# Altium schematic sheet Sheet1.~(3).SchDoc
size A4; SheetNumber: 1; SheetTotal: 1
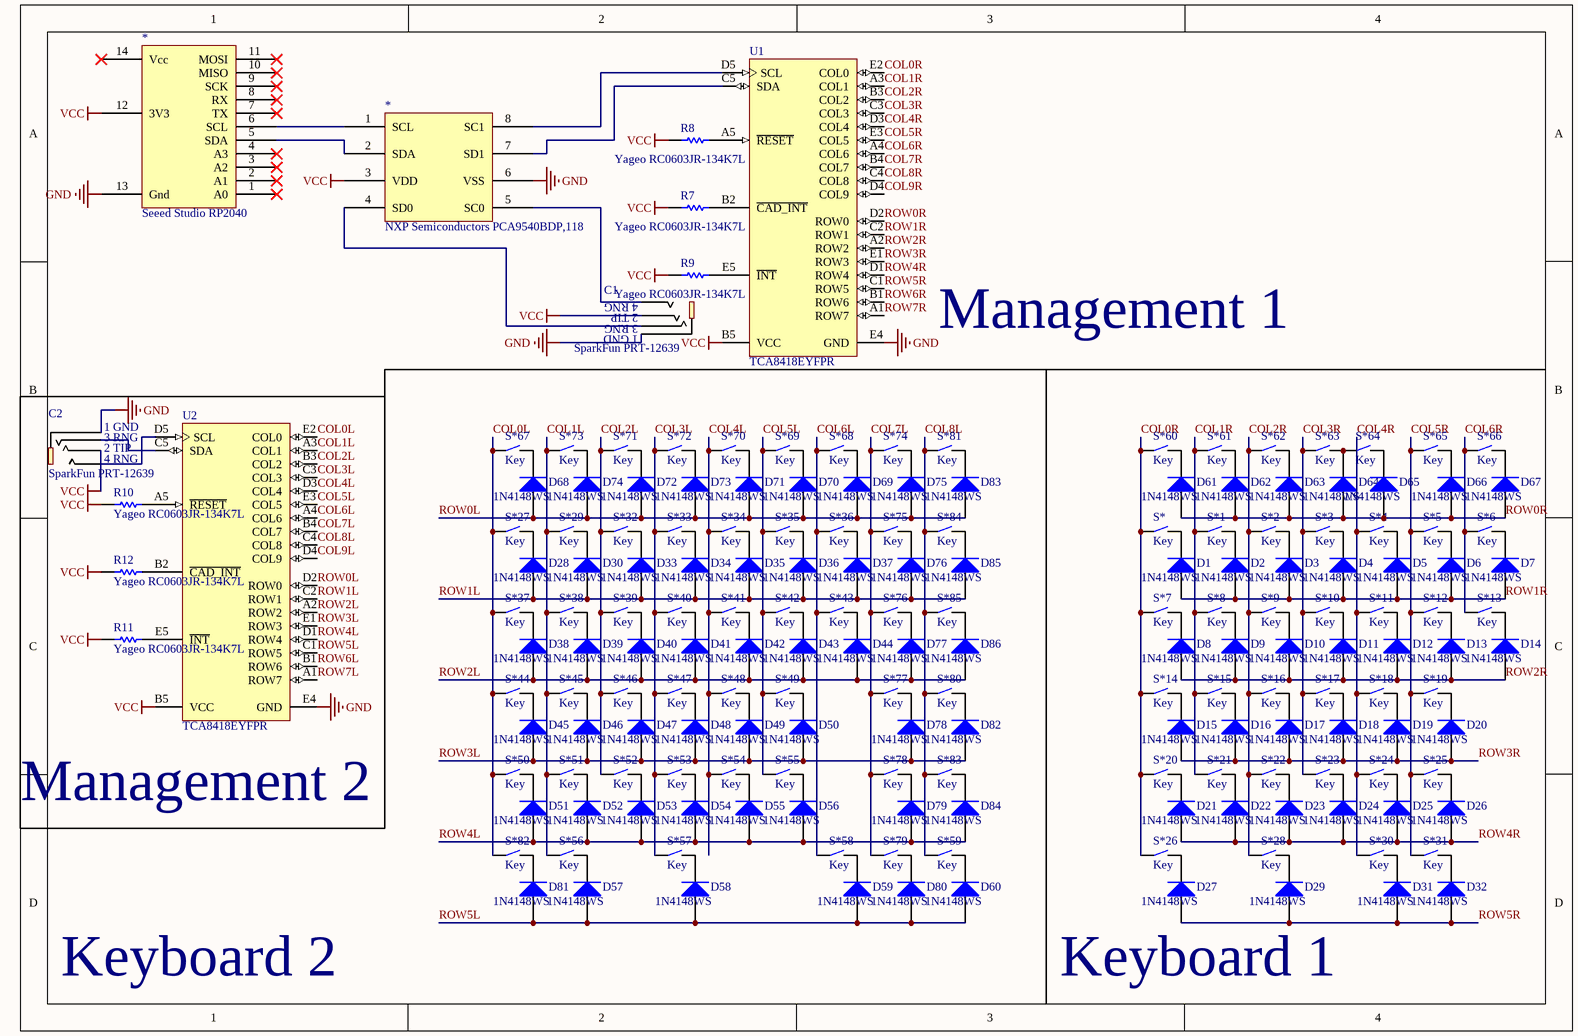
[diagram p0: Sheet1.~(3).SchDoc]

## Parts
(Parts that share a designator on the sheet are numbered #1, #2 ... from top to bottom, then left to right.)
*#1  Seeed Studio RP2040  [Seeed Studio 102010328-Footprint-2]
*#2  NXP Semiconductors PCA9540BDP,118  [TSSOP-ST8_M]
C1  SparkFun PRT-12639  [PCB-gnlnaqw4so214acln296-1]
C2  SparkFun PRT-12639  [PCB-gnlnaqw4so214acln296-1]
D1  1N4148WS  [SODFL250X100-2N]
D2  1N4148WS  [SODFL250X100-2N]
D3  1N4148WS  [SODFL250X100-2N]
D4  1N4148WS  [SODFL250X100-2N]
D5  1N4148WS  [SODFL250X100-2N]
D6  1N4148WS  [SODFL250X100-2N]
D7  1N4148WS  [SODFL250X100-2N]
D8  1N4148WS  [SODFL250X100-2N]
D9  1N4148WS  [SODFL250X100-2N]
D10  1N4148WS  [SODFL250X100-2N]
D11  1N4148WS  [SODFL250X100-2N]
D12  1N4148WS  [SODFL250X100-2N]
D13  1N4148WS  [SODFL250X100-2N]
D14  1N4148WS  [SODFL250X100-2N]
D15  1N4148WS  [SODFL250X100-2N]
D16  1N4148WS  [SODFL250X100-2N]
D17  1N4148WS  [SODFL250X100-2N]
D18  1N4148WS  [SODFL250X100-2N]
D19  1N4148WS  [SODFL250X100-2N]
D20  1N4148WS  [SODFL250X100-2N]
D21  1N4148WS  [SODFL250X100-2N]
D22  1N4148WS  [SODFL250X100-2N]
D23  1N4148WS  [SODFL250X100-2N]
D24  1N4148WS  [SODFL250X100-2N]
D25  1N4148WS  [SODFL250X100-2N]
D26  1N4148WS  [SODFL250X100-2N]
D27  1N4148WS  [SODFL250X100-2N]
D28  1N4148WS  [SODFL250X100-2N]
D29  1N4148WS  [SODFL250X100-2N]
D30  1N4148WS  [SODFL250X100-2N]
D31  1N4148WS  [SODFL250X100-2N]
D32  1N4148WS  [SODFL250X100-2N]
D33  1N4148WS  [SODFL250X100-2N]
D34  1N4148WS  [SODFL250X100-2N]
D35  1N4148WS  [SODFL250X100-2N]
D36  1N4148WS  [SODFL250X100-2N]
D37  1N4148WS  [SODFL250X100-2N]
D38  1N4148WS  [SODFL250X100-2N]
D39  1N4148WS  [SODFL250X100-2N]
D40  1N4148WS  [SODFL250X100-2N]
D41  1N4148WS  [SODFL250X100-2N]
D42  1N4148WS  [SODFL250X100-2N]
D43  1N4148WS  [SODFL250X100-2N]
D44  1N4148WS  [SODFL250X100-2N]
D45  1N4148WS  [SODFL250X100-2N]
D46  1N4148WS  [SODFL250X100-2N]
D47  1N4148WS  [SODFL250X100-2N]
D48  1N4148WS  [SODFL250X100-2N]
D49  1N4148WS  [SODFL250X100-2N]
D50  1N4148WS  [SODFL250X100-2N]
D51  1N4148WS  [SODFL250X100-2N]
D52  1N4148WS  [SODFL250X100-2N]
D53  1N4148WS  [SODFL250X100-2N]
D54  1N4148WS  [SODFL250X100-2N]
D55  1N4148WS  [SODFL250X100-2N]
D56  1N4148WS  [SODFL250X100-2N]
D57  1N4148WS  [SODFL250X100-2N]
D58  1N4148WS  [SODFL250X100-2N]
D59  1N4148WS  [SODFL250X100-2N]
D60  1N4148WS  [SODFL250X100-2N]
D61  1N4148WS  [SODFL250X100-2N]
D62  1N4148WS  [SODFL250X100-2N]
D63  1N4148WS  [SODFL250X100-2N]
D64  1N4148WS  [SODFL250X100-2N]
D65  1N4148WS  [SODFL250X100-2N]
D66  1N4148WS  [SODFL250X100-2N]
D67  1N4148WS  [SODFL250X100-2N]
D68  1N4148WS  [SODFL250X100-2N]
D69  1N4148WS  [SODFL250X100-2N]
D70  1N4148WS  [SODFL250X100-2N]
D71  1N4148WS  [SODFL250X100-2N]
D72  1N4148WS  [SODFL250X100-2N]
D73  1N4148WS  [SODFL250X100-2N]
D74  1N4148WS  [SODFL250X100-2N]
D75  1N4148WS  [SODFL250X100-2N]
D76  1N4148WS  [SODFL250X100-2N]
D77  1N4148WS  [SODFL250X100-2N]
D78  1N4148WS  [SODFL250X100-2N]
D79  1N4148WS  [SODFL250X100-2N]
D80  1N4148WS  [SODFL250X100-2N]
D81  1N4148WS  [SODFL250X100-2N]
D82  1N4148WS  [SODFL250X100-2N]
D83  1N4148WS  [SODFL250X100-2N]
D84  1N4148WS  [SODFL250X100-2N]
D85  1N4148WS  [SODFL250X100-2N]
D86  1N4148WS  [SODFL250X100-2N]
R7  Yageo RC0603JR-134K7L  [RESC1608X55X25LL10T15]
R8  Yageo RC0603JR-134K7L  [RESC1608X55X25LL10T15]
R9  Yageo RC0603JR-134K7L  [RESC1608X55X25LL10T15]
R10  Yageo RC0603JR-134K7L  [RESC1608X55X25LL10T15]
R11  Yageo RC0603JR-134K7L  [RESC1608X55X25LL10T15]
R12  Yageo RC0603JR-134K7L  [RESC1608X55X25LL10T15]
S*  Key  [Adafruit Industries 4958-Footprint-1]
S*1  Key  [Adafruit Industries 4958-Footprint-1]
S*2  Key  [Adafruit Industries 4958-Footprint-1]
S*3  Key  [Adafruit Industries 4958-Footprint-1]
S*4  Key  [Adafruit Industries 4958-Footprint-1]
S*5  Key  [Adafruit Industries 4958-Footprint-1]
S*6  Key  [Adafruit Industries 4958-Footprint-1]
S*7  Key  [Adafruit Industries 4958-Footprint-1]
S*8  Key  [Adafruit Industries 4958-Footprint-1]
S*9  Key  [Adafruit Industries 4958-Footprint-1]
S*10  Key  [Adafruit Industries 4958-Footprint-1]
S*11  Key  [Adafruit Industries 4958-Footprint-1]
S*12  Key  [Adafruit Industries 4958-Footprint-1]
S*13  Key  [Adafruit Industries 4958-Footprint-1]
S*14  Key  [Adafruit Industries 4958-Footprint-1]
S*15  Key  [Adafruit Industries 4958-Footprint-1]
S*16  Key  [Adafruit Industries 4958-Footprint-1]
S*17  Key  [Adafruit Industries 4958-Footprint-1]
S*18  Key  [Adafruit Industries 4958-Footprint-1]
S*19  Key  [Adafruit Industries 4958-Footprint-1]
S*20  Key  [Adafruit Industries 4958-Footprint-1]
S*21  Key  [Adafruit Industries 4958-Footprint-1]
S*22  Key  [Adafruit Industries 4958-Footprint-1]
S*23  Key  [Adafruit Industries 4958-Footprint-1]
S*24  Key  [Adafruit Industries 4958-Footprint-1]
S*25  Key  [Adafruit Industries 4958-Footprint-1]
S*26  Key  [Adafruit Industries 4958-Footprint-1]
S*27  Key  [Adafruit Industries 4958-Footprint-1]
S*28  Key  [Adafruit Industries 4958-Footprint-1]
S*29  Key  [Adafruit Industries 4958-Footprint-1]
S*30  Key  [Adafruit Industries 4958-Footprint-1]
S*31  Key  [Adafruit Industries 4958-Footprint-1]
S*32  Key  [Adafruit Industries 4958-Footprint-1]
S*33  Key  [Adafruit Industries 4958-Footprint-1]
S*34  Key  [Adafruit Industries 4958-Footprint-1]
S*35  Key  [Adafruit Industries 4958-Footprint-1]
S*36  Key  [Adafruit Industries 4958-Footprint-1]
S*37  Key  [Adafruit Industries 4958-Footprint-1]
S*38  Key  [Adafruit Industries 4958-Footprint-1]
S*39  Key  [Adafruit Industries 4958-Footprint-1]
S*40  Key  [Adafruit Industries 4958-Footprint-1]
S*41  Key  [Adafruit Industries 4958-Footprint-1]
S*42  Key  [Adafruit Industries 4958-Footprint-1]
S*43  Key  [Adafruit Industries 4958-Footprint-1]
S*44  Key  [Adafruit Industries 4958-Footprint-1]
S*45  Key  [Adafruit Industries 4958-Footprint-1]
S*46  Key  [Adafruit Industries 4958-Footprint-1]
S*47  Key  [Adafruit Industries 4958-Footprint-1]
S*48  Key  [Adafruit Industries 4958-Footprint-1]
S*49  Key  [Adafruit Industries 4958-Footprint-1]
S*50  Key  [Adafruit Industries 4958-Footprint-1]
S*51  Key  [Adafruit Industries 4958-Footprint-1]
S*52  Key  [Adafruit Industries 4958-Footprint-1]
S*53  Key  [Adafruit Industries 4958-Footprint-1]
S*54  Key  [Adafruit Industries 4958-Footprint-1]
S*55  Key  [Adafruit Industries 4958-Footprint-1]
S*56  Key  [Adafruit Industries 4958-Footprint-1]
S*57  Key  [Adafruit Industries 4958-Footprint-1]
S*58  Key  [Adafruit Industries 4958-Footprint-1]
S*59  Key  [Adafruit Industries 4958-Footprint-1]
S*60  Key  [Adafruit Industries 4958-Footprint-1]
S*61  Key  [Adafruit Industries 4958-Footprint-1]
S*62  Key  [Adafruit Industries 4958-Footprint-1]
S*63  Key  [Adafruit Industries 4958-Footprint-1]
S*64  Key  [Adafruit Industries 4958-Footprint-1]
S*65  Key  [Adafruit Industries 4958-Footprint-1]
S*66  Key  [Adafruit Industries 4958-Footprint-1]
S*67  Key  [Adafruit Industries 4958-Footprint-1]
S*68  Key  [Adafruit Industries 4958-Footprint-1]
S*69  Key  [Adafruit Industries 4958-Footprint-1]
S*70  Key  [Adafruit Industries 4958-Footprint-1]
S*71  Key  [Adafruit Industries 4958-Footprint-1]
S*72  Key  [Adafruit Industries 4958-Footprint-1]
S*73  Key  [Adafruit Industries 4958-Footprint-1]
S*74  Key  [Adafruit Industries 4958-Footprint-1]
S*75  Key  [Adafruit Industries 4958-Footprint-1]
S*76  Key  [Adafruit Industries 4958-Footprint-1]
S*77  Key  [Adafruit Industries 4958-Footprint-1]
S*78  Key  [Adafruit Industries 4958-Footprint-1]
S*79  Key  [Adafruit Industries 4958-Footprint-1]
S*80  Key  [Adafruit Industries 4958-Footprint-1]
S*81  Key  [Adafruit Industries 4958-Footprint-1]
S*82  Key  [Adafruit Industries 4958-Footprint-1]
S*83  Key  [Adafruit Industries 4958-Footprint-1]
S*84  Key  [Adafruit Industries 4958-Footprint-1]
S*85  Key  [Adafruit Industries 4958-Footprint-1]
U1  TCA8418EYFPR  [YFP25]
U2  TCA8418EYFPR  [YFP25]

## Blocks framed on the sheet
Management 2: C2 R10-R12 U2

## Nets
GND: *#1.13(Gnd) *#2.6(VSS) C1.4 C2.4 U1.E4(GND) U2.E4(GND)
VCC: *#1.12(3V3) *#2.3(VDD) C1.2 C2.1 C2.2 R7.1 R8.1 R9.1 R10.1 R11.1 R12.1 U1.B5(VCC) U2.B5(VCC) U2.D5(SCL)
COL0L: S*27.1 S*37.1 S*44.1 S*50.1 S*67.1 S*82.1 U2.E2(COL0)
COL0R: S*.1 S*7.1 S*14.1 S*20.1 S*26.1 S*60.1 U1.E2(COL0)
COL1L: S*29.1 S*38.1 S*45.1 S*51.1 S*56.1 S*73.1 U2.A3(COL1)
COL1R: S*1.1 S*8.1 S*15.1 S*21.1 S*61.1 U1.A3(COL1)
COL2L: S*32.1 S*39.1 S*46.1 S*52.1 S*71.1 U2.B3(COL2)
COL2R: S*2.1 S*9.1 S*16.1 S*22.1 S*28.1 S*62.1 U1.B3(COL2)
COL3L: S*33.1 S*40.1 S*47.1 S*53.1 S*57.1 S*72.1 U2.C3(COL3)
COL3R: S*3.1 S*10.1 S*17.1 S*23.1 S*63.1 U1.C3(COL3)
COL4L: S*34.1 S*41.1 S*48.1 S*54.1 S*70.1 U2.D3(COL4)
COL4R: S*4.1 S*11.1 S*18.1 S*24.1 S*30.1 U1.D3(COL4)
COL5L: S*35.1 S*42.1 S*49.1 S*55.1 S*69.1 U2.E3(COL5)
COL5R: S*5.1 S*12.1 S*19.1 S*25.1 S*31.1 S*65.1 U1.E3(COL5)
COL6L: S*36.1 S*43.1 S*58.1 S*68.1 U2.A4(COL6)
COL6R: S*6.1 S*13.1 S*66.1 U1.A4(COL6)
COL7L: S*74.1 S*75.1 S*76.1 S*77.1 S*78.1 S*79.1 U2.B4(COL7)
COL7R: U1.B4(COL7)
COL8L: S*59.1 S*80.1 S*81.1 S*83.1 S*84.1 S*85.1 U2.C4(COL8)
COL8R: U1.C4(COL8)
COL9L: U2.D4(COL9)
COL9R: U1.D4(COL9)
ROW0L: D68.1(A) D69.1(A) D70.1(A) D71.1(A) D72.1(A) D73.1(A) D74.1(A) D75.1(A) D83.1(A) U2.D2(ROW0)
ROW0R: D61.1(A) D62.1(A) D63.1(A) D64.1(A) D65.1(A) D66.1(A) D67.1(A) U1.D2(ROW0)
ROW1L: D28.1(A) D30.1(A) D33.1(A) D34.1(A) D35.1(A) D36.1(A) D37.1(A) D76.1(A) D85.1(A) U2.C2(ROW1)
ROW1R: D1.1(A) D2.1(A) D3.1(A) D4.1(A) D5.1(A) D6.1(A) D7.1(A) U1.C2(ROW1)
ROW2L: D38.1(A) D39.1(A) D40.1(A) D41.1(A) D42.1(A) D43.1(A) D44.1(A) D77.1(A) D86.1(A) U2.A2(ROW2)
ROW2R: D8.1(A) D9.1(A) D10.1(A) D11.1(A) D12.1(A) D13.1(A) D14.1(A) U1.A2(ROW2)
ROW3L: D45.1(A) D46.1(A) D47.1(A) D48.1(A) D49.1(A) D50.1(A) D78.1(A) D82.1(A) U2.E1(ROW3)
ROW3R: D15.1(A) D16.1(A) D17.1(A) D18.1(A) D19.1(A) D20.1(A) U1.E1(ROW3)
ROW4L: D51.1(A) D52.1(A) D53.1(A) D54.1(A) D55.1(A) D56.1(A) D79.1(A) D84.1(A) U2.D1(ROW4)
ROW4R: D21.1(A) D22.1(A) D23.1(A) D24.1(A) D25.1(A) D26.1(A) U1.D1(ROW4)
ROW5L: D57.1(A) D58.1(A) D59.1(A) D60.1(A) D80.1(A) D81.1(A) U2.C1(ROW5)
ROW5R: D27.1(A) D29.1(A) D31.1(A) D32.1(A) U1.C1(ROW5)
ROW6L: U2.B1(ROW6)
ROW6R: U1.B1(ROW6)
ROW7L: U2.A1(ROW7)
ROW7R: U1.A1(ROW7)
Net*#1_5: *#1.5(SDA) *#2.2(SDA)
Net*#1_6: *#1.6(SCL) *#2.1(SCL)
Net*#2_4: *#2.4(SD0) C1.3
Net*#2_5: *#2.5(SC0) C1.1
Net*#2_7: *#2.7(SD1) U1.C5(SDA)
Net*#2_8: *#2.8(SC1) U1.D5(SCL)
NetC2_3: C2.3 U2.C5(SDA)
NetD1_2: D1.2(K) S*.2
NetD2_2: D2.2(K) S*1.2
NetD3_2: D3.2(K) S*2.2
NetD4_2: D4.2(K) S*3.2
NetD5_2: D5.2(K) S*4.2
NetD6_2: D6.2(K) S*5.2
NetD7_2: D7.2(K) S*6.2
NetD8_2: D8.2(K) S*7.2
NetD9_2: D9.2(K) S*8.2
NetD10_2: D10.2(K) S*9.2
NetD11_2: D11.2(K) S*10.2
NetD12_2: D12.2(K) S*11.2
NetD13_2: D13.2(K) S*12.2
NetD14_2: D14.2(K) S*13.2
NetD15_2: D15.2(K) S*14.2
NetD16_2: D16.2(K) S*15.2
NetD17_2: D17.2(K) S*16.2
NetD18_2: D18.2(K) S*17.2
NetD19_2: D19.2(K) S*18.2
NetD20_2: D20.2(K) S*19.2
NetD21_2: D21.2(K) S*20.2
NetD22_2: D22.2(K) S*21.2
NetD23_2: D23.2(K) S*22.2
NetD24_2: D24.2(K) S*23.2
NetD25_2: D25.2(K) S*24.2
NetD26_2: D26.2(K) S*25.2
NetD27_2: D27.2(K) S*26.2
NetD28_2: D28.2(K) S*27.2
NetD29_2: D29.2(K) S*28.2
NetD30_2: D30.2(K) S*29.2
NetD31_2: D31.2(K) S*30.2
NetD32_2: D32.2(K) S*31.2
NetD33_2: D33.2(K) S*32.2
NetD34_2: D34.2(K) S*33.2
NetD35_2: D35.2(K) S*34.2
NetD36_2: D36.2(K) S*35.2
NetD37_2: D37.2(K) S*36.2
NetD38_2: D38.2(K) S*37.2
NetD39_2: D39.2(K) S*38.2
NetD40_2: D40.2(K) S*39.2
NetD41_2: D41.2(K) S*40.2
NetD42_2: D42.2(K) S*41.2
NetD43_2: D43.2(K) S*42.2
NetD44_2: D44.2(K) S*43.2
NetD45_2: D45.2(K) S*44.2
NetD46_2: D46.2(K) S*45.2
NetD47_2: D47.2(K) S*46.2
NetD48_2: D48.2(K) S*47.2
NetD49_2: D49.2(K) S*48.2
NetD50_2: D50.2(K) S*49.2
NetD51_2: D51.2(K) S*50.2
NetD52_2: D52.2(K) S*51.2
NetD53_2: D53.2(K) S*52.2
NetD54_2: D54.2(K) S*53.2
NetD55_2: D55.2(K) S*54.2
NetD56_2: D56.2(K) S*55.2
NetD57_2: D57.2(K) S*56.2
NetD58_2: D58.2(K) S*57.2
NetD59_2: D59.2(K) S*58.2
NetD60_2: D60.2(K) S*59.2
NetD61_2: D61.2(K) S*60.2
NetD62_2: D62.2(K) S*61.2
NetD63_2: D63.2(K) S*62.2
NetD64_2: D64.2(K) S*63.2 S*64.1
NetD65_2: D65.2(K) S*64.2
NetD66_2: D66.2(K) S*65.2
NetD67_2: D67.2(K) S*66.2
NetD68_2: D68.2(K) S*67.2
NetD69_2: D69.2(K) S*68.2
NetD70_2: D70.2(K) S*69.2
NetD71_2: D71.2(K) S*70.2
NetD72_2: D72.2(K) S*71.2
NetD73_2: D73.2(K) S*72.2
NetD74_2: D74.2(K) S*73.2
NetD75_2: D75.2(K) S*74.2
NetD76_2: D76.2(K) S*75.2
NetD77_2: D77.2(K) S*76.2
NetD78_2: D78.2(K) S*77.2
NetD79_2: D79.2(K) S*78.2
NetD80_2: D80.2(K) S*79.2
NetD81_2: D81.2(K) S*82.2
NetD82_2: D82.2(K) S*80.2
NetD83_2: D83.2(K) S*81.2
NetD84_2: D84.2(K) S*83.2
NetD85_2: D85.2(K) S*84.2
NetD86_2: D86.2(K) S*85.2
NetR7_2: R7.2 U1.B2(~{CAD_INT})
NetR8_2: R8.2 U1.A5(~{RESET})
NetR9_2: R9.2 U1.E5(~{INT})
NetR10_2: R10.2 U2.A5(~{RESET})
NetR11_2: R11.2 U2.E5(~{INT})
NetR12_2: R12.2 U2.B2(~{CAD_INT})

Not connected (* = marked no-connect by the designer): *#1 1(A0)* 2(A1)* 3(A2)* 4(A3)* 7(TX)* 8(RX)* 9(SCK)* 10(MISO)* 11(MOSI)* 14(Vcc)*

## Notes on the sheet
- Management 1
- Keyboard 2
- Keyboard 1

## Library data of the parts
*#1 = CMP-b80e762cf75067c9-4: Seeed Xiao RP2040 - Supports Ard; Manufacturer Part Number: 102010428
*#2 = CMP-7778beedef95a8bf-1: PCA9540 Series 2-Channel I2C Bidirectional Translating Multiplexer - TSSOP-8; Lead-Free Status: Lead Free; Supply Voltage (DC): 5.50 V (max), 2.30 V (min); Supply Current: 20.0 µA
C1 C2 = CMP-83844e03d9af5c43-1: SparkFun Audio Jack - 3.5mm TRRS (SMD) 4 Position
D1-D86 = CMP-814637-10: Small Signal Diode, 75 V, 0.15 A, -55 to 150 degC, 2-Pin SOD-323, RoHS, Tape and Reel; Lead-Free Status: Lead Free
R7-R12 = CMP-3759266-2: YAGEO   RC0603JR-134K7L   THICK FILM RESISTOR, 4.7KOHM, 100mW, 5%; Lead-Free Status: Lead Free; Power Rating: 0.1 W; Resistance: 4700.0 Ω; Voltage Rating (DC): 50.0 V
S* S*1-S*85 = CMP-2c34e3c0207ef3f3-5: Kailh Switch Sockets for MX-compatible Mechanical Keys - 20 Pack; Manufacturer Part Number: 4958
U1 U2 = CMP-19303953-2: I2C Controlled Keypad Scan IC with integrated ESD Protection, 1.65 to 3.6 V, -40 to 85 degC, 25-pin DSBGA (YFP), Green (RoHS & no Sb/Br); Lead-Free Status: Lead Free; Number of Outputs: 18; Propagation Delay Max (tpd): 1.2e-07 s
